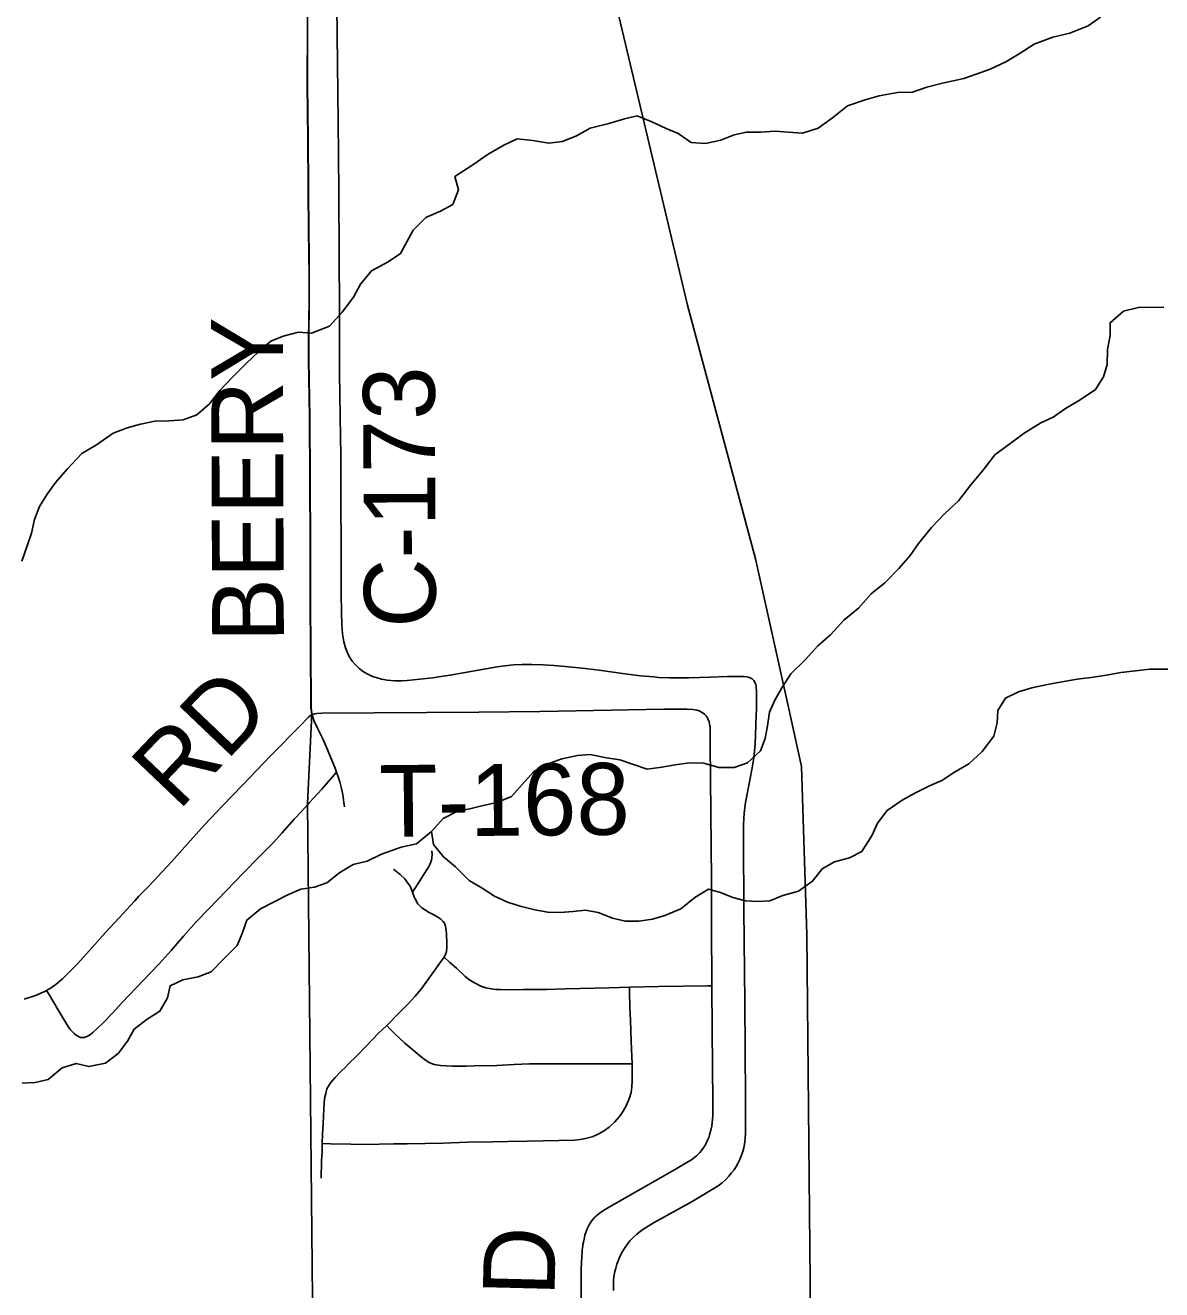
# Model space of a CAD drawing. Extents: x 0 to 34, y 0 to 22.
# Drawn here: x 27.697 to 28.598, y 10.604 to 11.606 of the extents above; entities that cross this region are included whole.
import ezdxf

# ---------------------------------------------------------------- set-up
doc = ezdxf.new("R2010")
doc.units = 0
for name, color, linetype in [('GM_X_Corporation', 7, 'Continuous'), ('GM_X_County_Road', 7, 'Continuous'), ('GM_X_County_Road_Text', 7, 'Continuous'), ('GM_X_Minor_River', 7, 'Continuous'), ('GM_X_Rail_Line', 7, 'Continuous'), ('GM_X_Township_Road', 7, 'Continuous'), ('GM_X_Township_Road_Text', 7, 'Continuous')]:
    doc.layers.add(name, color=color, linetype=linetype)

msp = doc.modelspace()

# ---------------------------------------------------------------- linework, layer by layer
at = {"layer": 'GM_X_Corporation'}
for points in [[(27.921, 11.6881), (27.921, 11.605), (27.9209, 11.5591), (27.9213, 11.5157), (27.922, 11.4402), (27.9221, 11.428), (27.9223, 11.4042), (27.9223, 11.3879), (27.922, 11.3573), (27.922, 11.3409), (27.9227, 11.2961), (27.9232, 11.1955), (27.9232, 11.1514), (27.9237, 11.0691), (27.9238, 11.0659), (27.9241, 11.0633), (27.9246, 11.0606), (27.9211, 10.9894), (27.9256, 10.5454), (27.929, 10.0627), (27.93, 9.9067), (29.8715, 9.9067), (29.8715, 12.7899)], [(23.0715, 9.9067), (27.93, 9.9067), (27.929, 10.0627), (27.9256, 10.5454), (27.9211, 10.9894), (27.9246, 11.0606), (27.9241, 11.0633), (27.9238, 11.0659), (27.9237, 11.0691), (27.9232, 11.1514), (27.9232, 11.1955), (27.9227, 11.2961), (27.922, 11.3409), (27.922, 11.3573), (27.9223, 11.3879), (27.9223, 11.4042), (27.9221, 11.428), (27.922, 11.4402), (27.9213, 11.5157), (27.9209, 11.5591), (27.921, 11.605), (27.921, 11.6881)]]:
    msp.add_lwpolyline(points, dxfattribs=at)
at = {"layer": 'GM_X_County_Road'}
for points in [[(27.9248, 11.06), (27.9243, 11.0628), (27.924, 11.0654), (27.9239, 11.0685), (27.9234, 11.1508), (27.9234, 11.1949), (27.9229, 11.2955), (27.9222, 11.3403), (27.9222, 11.3568), (27.9225, 11.3874), (27.9225, 11.4036), (27.9223, 11.4275), (27.9222, 11.4396), (27.9215, 11.5151), (27.9211, 11.5586), (27.9212, 11.6045), (27.9212, 11.6876)], [(27.7142, 10.8413), (27.7179, 10.8436), (27.7219, 10.8464), (27.727, 10.8507), (27.7388, 10.8625), (27.7505, 10.8754), (27.7608, 10.887), (27.7718, 10.8989), (27.7805, 10.9084), (27.7842, 10.9125), (27.7875, 10.9161), (27.7886, 10.9171), (27.7944, 10.9229), (27.7996, 10.9284), (27.8057, 10.9351), (27.8136, 10.9435), (27.8219, 10.9527), (27.8396, 10.9726), (27.8541, 10.9879), (27.8696, 11.0039), (27.892, 11.0276), (27.9161, 11.0518), (27.9205, 11.0566), (27.9219, 11.058), (27.9234, 11.0593), (27.9248, 11.06)], [(27.9441, 11.0143), (27.9429, 11.0175), (27.9396, 11.0257), (27.9371, 11.0316), (27.9332, 11.0406), (27.9289, 11.0492), (27.9264, 11.0547), (27.9255, 11.0572), (27.9248, 11.06)], [(27.9207, 10.9881), (27.9213, 10.9888), (27.9226, 10.9902), (27.9261, 10.9941), (27.9325, 11.0008), (27.941, 11.0107), (27.9441, 11.0143)], [(27.9505, 10.9869), (27.95, 10.9903), (27.949, 10.9966), (27.948, 11.0013), (27.9466, 11.0066), (27.9454, 11.0105), (27.9441, 11.0143)], [(27.7396, 10.8049), (27.7413, 10.8043), (27.7429, 10.8042), (27.7445, 10.8043), (27.7455, 10.8046), (27.7477, 10.8056), (27.7507, 10.8078), (27.7543, 10.8111), (27.7592, 10.8159), (27.7665, 10.8235), (27.7741, 10.8315), (27.7912, 10.8495), (27.8036, 10.8624), (27.8131, 10.873), (27.8229, 10.8844), (27.833, 10.8957), (27.8429, 10.906), (27.8567, 10.9203), (27.8704, 10.9346), (27.8828, 10.9472), (27.8941, 10.9585), (27.9007, 10.9659), (27.9105, 10.977), (27.9162, 10.9832), (27.9186, 10.9858), (27.9207, 10.9881)], [(28.0042, 10.9192), (28.0057, 10.9214), (28.0101, 10.9283), (28.013, 10.9329), (28.0165, 10.9384), (28.017, 10.9391), (28.0179, 10.9411), (28.0193, 10.9445), (28.0196, 10.9465), (28.0199, 10.9491), (28.0196, 10.952)], [(28.0042, 10.9192), (28.004, 10.92), (28.0036, 10.9213), (28.0024, 10.9239), (28.0007, 10.9265), (27.9981, 10.9299), (27.9944, 10.9332), (27.9892, 10.9376)], [(28.0293, 10.8678), (28.0308, 10.8707), (28.0313, 10.8724), (28.0315, 10.8754), (28.0314, 10.8807), (28.0313, 10.884), (28.0312, 10.8864), (28.031, 10.8888), (28.0304, 10.8924), (28.0297, 10.8946), (28.0286, 10.896), (28.0268, 10.8978), (28.0243, 10.8996), (28.0217, 10.9011), (28.0176, 10.9032), (28.0137, 10.9055), (28.0118, 10.9068), (28.01, 10.9085), (28.0086, 10.9101), (28.0063, 10.9139), (28.0056, 10.9156), (28.0045, 10.9184), (28.0042, 10.9192)], [(27.9839, 10.8137), (27.9861, 10.8158), (27.9918, 10.8218), (28.0014, 10.8314), (28.0062, 10.8366), (28.0111, 10.8425), (28.0165, 10.8499), (28.0226, 10.8584), (28.0261, 10.8635), (28.0293, 10.8678)], [(28.0293, 10.8678), (28.0339, 10.8637), (28.0391, 10.859), (28.0461, 10.8524), (28.0497, 10.8497), (28.054, 10.8472), (28.0585, 10.8449), (28.0623, 10.8435), (28.0665, 10.8428), (28.0702, 10.8423), (28.074, 10.8421), (28.0833, 10.8419), (28.092, 10.8421), (28.1105, 10.8422), (28.1254, 10.8426), (28.1602, 10.8435), (28.1762, 10.844)], [(27.6965, 10.8346), (27.7064, 10.8378), (27.7098, 10.8392), (27.7134, 10.8408), (27.7142, 10.8413)], [(27.7396, 10.8049), (27.7377, 10.806), (27.7361, 10.8074), (27.7345, 10.8089), (27.733, 10.8106), (27.7315, 10.8129), (27.7293, 10.8164), (27.7231, 10.8268), (27.7178, 10.8358), (27.7171, 10.8368), (27.7142, 10.8413)], [(28.1762, 10.844), (28.1993, 10.8446), (28.2379, 10.8451), (28.2415, 10.8452)], [(28.1782, 10.7834), (28.1781, 10.7891), (28.1779, 10.7952), (28.1776, 10.8013), (28.177, 10.818), (28.1766, 10.8278), (28.1763, 10.8407), (28.1762, 10.844)], [(27.9326, 10.7201), (27.9331, 10.728), (27.9335, 10.7357), (27.9338, 10.7421), (27.9339, 10.7475), (27.9344, 10.7525), (27.9346, 10.7559), (27.9355, 10.7599), (27.9364, 10.7636), (27.9392, 10.7682), (27.9429, 10.7724), (27.9478, 10.7775), (27.9511, 10.7808), (27.9536, 10.7832), (27.96, 10.7895), (27.9676, 10.7972), (27.9773, 10.8075), (27.9808, 10.8109), (27.9839, 10.8137)], [(27.9839, 10.8137), (27.9864, 10.8111), (27.9905, 10.8068), (27.994, 10.8036), (27.9982, 10.7998), (28.0015, 10.797), (28.0046, 10.7943), (28.0097, 10.79), (28.0135, 10.7869), (28.0154, 10.7857), (28.018, 10.7842), (28.0215, 10.7828), (28.0265, 10.782), (28.036, 10.7814), (28.0467, 10.7814), (28.0534, 10.7816), (28.0711, 10.7821), (28.0847, 10.7829), (28.097, 10.7832), (28.1106, 10.7834), (28.1174, 10.7834), (28.1254, 10.7834), (28.1515, 10.7834), (28.1638, 10.7834), (28.1699, 10.7834), (28.1782, 10.7834)], [(27.9326, 10.7201), (27.9392, 10.72), (27.9555, 10.7196), (27.9665, 10.7195), (27.9895, 10.7199), (28.0001, 10.72), (28.0285, 10.7205), (28.0479, 10.7213), (28.068, 10.7216), (28.0799, 10.7217), (28.095, 10.722), (28.1327, 10.7229), (28.137, 10.7234), (28.1413, 10.7242), (28.1467, 10.7256), (28.1513, 10.7275), (28.1556, 10.7299), (28.1602, 10.7332), (28.1647, 10.7374), (28.1684, 10.7416), (28.1712, 10.7458), (28.1737, 10.7507), (28.1762, 10.7564), (28.1774, 10.7606), (28.178, 10.7649), (28.1783, 10.7705), (28.1782, 10.7834)], [(27.9319, 10.6927), (27.9323, 10.7064), (27.9327, 10.7138), (27.9326, 10.7187), (27.9326, 10.7201)]]:
    msp.add_lwpolyline(points, dxfattribs=at)
at = {"layer": 'GM_X_Minor_River'}
for points in [[(28.5116, 11.5964), (28.5252, 11.5996), (28.5395, 11.6055), (28.5493, 11.6124)], [(27.6948, 11.1814), (27.6989, 11.1936), (27.7025, 11.2035), (27.7047, 11.2145), (27.7087, 11.2248), (27.7147, 11.2344), (27.7218, 11.244), (27.7307, 11.2543), (27.7423, 11.2666), (27.754, 11.2736), (27.7672, 11.2828), (27.7781, 11.2871), (27.7887, 11.2899), (27.8, 11.2923), (27.8114, 11.2925), (27.8227, 11.2934), (27.8333, 11.2973), (27.8434, 11.3061), (27.8516, 11.3165), (27.8621, 11.3276), (27.8726, 11.338), (27.8823, 11.3472), (27.8921, 11.3557), (27.9019, 11.3596), (27.914, 11.3628), (27.9242, 11.3621), (27.9385, 11.3676), (27.9486, 11.3787), (27.9576, 11.3906), (27.9631, 11.4009), (27.9717, 11.4113), (27.9849, 11.4186), (27.9947, 11.4252), (28.0047, 11.4436), (28.0148, 11.4535), (28.0265, 11.4586), (28.0363, 11.464), (28.0407, 11.4755), (28.0379, 11.4861), (28.0522, 11.4954), (28.0642, 11.5039), (28.0767, 11.5108), (28.0872, 11.5159), (28.0997, 11.5145), (28.1122, 11.5124), (28.1232, 11.5137), (28.1341, 11.5183), (28.1451, 11.5245), (28.1598, 11.5281), (28.1722, 11.5317), (28.1824, 11.5341), (28.1939, 11.5293), (28.2053, 11.5241), (28.2148, 11.5201), (28.2251, 11.513), (28.2365, 11.5123), (28.2486, 11.5148), (28.2591, 11.5191), (28.2689, 11.5211), (28.2799, 11.5212), (28.2917, 11.5221), (28.3019, 11.5211), (28.3133, 11.5204), (28.3257, 11.5244), (28.337, 11.5325), (28.349, 11.5421), (28.363, 11.5468), (28.3739, 11.55), (28.3886, 11.5525), (28.4004, 11.553), (28.4117, 11.5569), (28.4242, 11.5601), (28.4412, 11.5637), (28.451, 11.5672), (28.4619, 11.5712), (28.4743, 11.577), (28.4849, 11.5832), (28.4969, 11.5909), (28.5116, 11.5964)], [(28.4571, 11.2545), (28.4657, 11.2656), (28.4785, 11.2752), (28.489, 11.2829), (28.5022, 11.2911), (28.512, 11.2954), (28.5217, 11.3023), (28.5334, 11.3093), (28.5454, 11.3174), (28.5518, 11.3273), (28.5547, 11.3372), (28.5549, 11.349), (28.5571, 11.3601), (28.557, 11.3703), (28.5675, 11.3795), (28.5796, 11.3823), (28.5996, 11.3826)], [(27.6949, 10.7679), (27.7052, 10.7684), (27.7157, 10.7708), (27.7266, 10.7801), (27.7379, 10.7836), (27.7478, 10.7811), (27.761, 10.7839), (27.7712, 10.7916), (27.7786, 10.8012), (27.7838, 10.8107), (27.794, 10.8188), (27.8041, 10.825), (27.8101, 10.8357), (27.8122, 10.8452), (27.8224, 10.8499), (27.8345, 10.8523), (27.8447, 10.8562), (27.8548, 10.8666), (27.8653, 10.877), (27.8693, 10.8865), (27.873, 10.8972), (27.8839, 10.9061), (27.8937, 10.9111), (27.9061, 10.9173), (27.9159, 10.9216), (27.9265, 10.9233), (27.9363, 10.9268), (27.9468, 10.9349), (27.9573, 10.9411), (27.9683, 10.9439), (27.9796, 10.9493), (27.9954, 10.9548), (28.0075, 10.9576), (28.0192, 10.9672), (28.0285, 10.9776), (28.0398, 10.9834), (28.0496, 10.9854), (28.0602, 10.9879), (28.0712, 10.9903), (28.0828, 10.995), (28.0911, 11.0045), (28.1004, 11.0149), (28.111, 11.0207), (28.1227, 11.025), (28.1351, 11.0275), (28.145, 11.0283), (28.1579, 11.0258), (28.1685, 11.024), (28.1795, 11.0204), (28.1902, 11.0167), (28.2019, 11.0184), (28.2125, 11.02), (28.2238, 11.0217), (28.2352, 11.0214), (28.247, 11.0181), (28.2591, 11.0179), (28.2696, 11.0218), (28.2801, 11.0311), (28.2838, 11.041), (28.2856, 11.0509), (28.287, 11.0619), (28.2914, 11.0714), (28.297, 11.081), (28.3041, 11.0921), (28.3153, 11.1032), (28.3254, 11.1144), (28.3355, 11.1232), (28.346, 11.1347), (28.3576, 11.1443), (28.3677, 11.1555), (28.3786, 11.1643), (28.3895, 11.1755), (28.3985, 11.1858), (28.4052, 11.1954), (28.4156, 11.208), (28.4261, 11.2192), (28.437, 11.2292), (28.4467, 11.2418), (28.4571, 11.2545)], [(28.0192, 10.9672), (28.0208, 10.957), (28.0288, 10.9472), (28.0384, 10.9394), (28.0491, 10.9285), (28.0594, 10.9225), (28.0693, 10.9162), (28.0796, 10.9114), (28.0895, 10.9081), (28.1013, 10.9052), (28.1115, 10.9034), (28.1214, 10.9031), (28.1316, 10.904), (28.1414, 10.9049), (28.1513, 10.9031), (28.1627, 10.8987), (28.173, 10.8962), (28.1836, 10.8963), (28.1945, 10.8979), (28.2043, 10.9007), (28.2168, 10.9062), (28.228, 10.915), (28.2389, 10.9216), (28.2484, 10.9191), (28.258, 10.915), (28.2682, 10.9125), (28.2777, 10.9118), (28.2875, 10.9123), (28.2977, 10.9166), (28.3102, 10.9202), (28.3211, 10.9279), (28.3289, 10.9378), (28.3387, 10.9433), (28.3504, 10.9465), (28.3602, 10.9515), (28.3684, 10.9645), (28.3728, 10.974), (28.3803, 10.984), (28.3923, 10.9921), (28.4028, 10.9979), (28.4138, 11.0034), (28.4236, 11.0077), (28.4337, 11.0142), (28.445, 11.0208), (28.4555, 11.0308), (28.4648, 11.0427), (28.4674, 11.0534), (28.468, 11.0632), (28.474, 11.0728), (28.4845, 11.0779), (28.4951, 11.081), (28.5075, 11.0838), (28.5174, 11.0855), (28.531, 11.0879), (28.5419, 11.0892), (28.5525, 11.0908), (28.5654, 11.0932), (28.5771, 11.0945), (28.5885, 11.0958), (28.6028, 11.096)]]:
    msp.add_lwpolyline(points, dxfattribs=at)
at = {"layer": 'GM_X_Rail_Line'}
msp.add_lwpolyline([(28.1314, 11.7668), (28.2222, 11.3843), (28.276, 11.1832), (28.302, 11.0668), (28.3126, 11.0187), (28.3168, 10.8858), (28.3206, 10.4739), (28.3218, 10.0678), (28.3164, 10.0296), (28.3055, 9.997), (28.289, 9.9687), (28.2676, 9.9404), (28.2321, 9.9067)], dxfattribs=at)
at = {"layer": 'GM_X_Township_Road'}
for points in [[(28.2767, 11.0636), (28.2767, 11.0696), (28.2767, 11.0782), (28.2766, 11.0813), (28.2765, 11.0827), (28.2762, 11.0838), (28.2758, 11.0849), (28.2753, 11.086), (28.2746, 11.087), (28.2737, 11.0879), (28.2728, 11.0885), (28.2719, 11.089), (28.271, 11.0894), (28.2702, 11.0896), (28.2692, 11.0898), (28.2667, 11.0901), (28.2618, 11.0902), (28.2537, 11.09), (28.2401, 11.0895), (28.2233, 11.089), (28.2152, 11.089), (28.2115, 11.089), (28.2078, 11.0891), (28.1991, 11.0894), (28.1954, 11.0897), (28.1849, 11.0906), (28.1707, 11.0925), (28.1523, 11.0952), (28.1387, 11.0967), (28.1252, 11.098), (28.1166, 11.0987), (28.1077, 11.0993), (28.099, 11.0996), (28.0911, 11.0995), (28.0842, 11.0992), (28.0773, 11.0985), (28.0713, 11.0977), (28.0578, 11.0954), (28.034, 11.0912), (28.0285, 11.0903), (28.0236, 11.0896), (28.0205, 11.0891), (28.01, 11.0879), (28.0001, 11.087), (27.9958, 11.0867), (27.9902, 11.0866), (27.9841, 11.0872), (27.9798, 11.088), (27.9762, 11.089), (27.9727, 11.0902), (27.9693, 11.0917), (27.9655, 11.0939), (27.962, 11.0965), (27.9589, 11.0995), (27.9565, 11.1023), (27.9541, 11.106), (27.9527, 11.1088), (27.9512, 11.1128), (27.9499, 11.1176), (27.9489, 11.1238), (27.9483, 11.1312), (27.9479, 11.1411), (27.9478, 11.1554), (27.9478, 11.1685), (27.9478, 11.1803), (27.9477, 11.1883), (27.9474, 11.2329), (27.9476, 11.2509), (27.9476, 11.2657), (27.9473, 11.28), (27.9469, 11.2962), (27.9464, 11.3303), (27.9464, 11.3787), (27.946, 11.473), (27.9457, 11.5034), (27.9453, 11.5295), (27.9438, 11.6675)], [(27.9248, 11.06), (27.9266, 11.0605), (27.9285, 11.0609), (27.9325, 11.0611), (28.0568, 11.0619), (28.1051, 11.0624), (28.1197, 11.0627), (28.2035, 11.0642), (28.2161, 11.0643), (28.2217, 11.0642), (28.2263, 11.0639), (28.2295, 11.0634), (28.2313, 11.0628), (28.2325, 11.0623), (28.2336, 11.0617), (28.2347, 11.061), (28.2355, 11.0603), (28.2361, 11.0598), (28.2369, 11.0589), (28.2373, 11.0583)], [(28.1635, 10.6037), (28.1635, 10.6086), (28.1636, 10.6122), (28.1641, 10.6161), (28.1646, 10.6189), (28.1653, 10.6216), (28.1662, 10.6246), (28.1684, 10.63), (28.1699, 10.6333), (28.172, 10.6368), (28.1743, 10.6403), (28.1765, 10.6431), (28.1795, 10.646), (28.1817, 10.6481), (28.1837, 10.6497), (28.1869, 10.6522), (28.191, 10.6548), (28.1957, 10.6577), (28.2258, 10.6744), (28.2464, 10.6868), (28.2495, 10.6891), (28.2523, 10.6914), (28.255, 10.6944), (28.2571, 10.6969), (28.2591, 10.6993), (28.2607, 10.7019), (28.2621, 10.7043), (28.2636, 10.7075), (28.2648, 10.7104), (28.2659, 10.714), (28.2669, 10.7168), (28.2674, 10.7196), (28.2679, 10.7239), (28.2682, 10.729), (28.268, 10.756), (28.2676, 10.8322), (28.2668, 10.9056), (28.2666, 10.9604), (28.2666, 10.9671), (28.2666, 10.9725), (28.2668, 10.9773), (28.2671, 10.9822), (28.2682, 10.9902), (28.2701, 11.0012), (28.2725, 11.0134), (28.2733, 11.0177), (28.2747, 11.0256), (28.2753, 11.0312), (28.2757, 11.0367), (28.276, 11.0438), (28.2766, 11.0597), (28.2767, 11.0636)], [(28.2415, 10.8452), (28.2413, 10.8935), (28.2411, 10.9291), (28.2402, 11.036), (28.2402, 11.0475), (28.24, 11.0496), (28.24, 11.0503), (28.2399, 11.051), (28.2397, 11.0524), (28.2392, 11.0545), (28.2389, 11.0552), (28.2383, 11.0565), (28.2377, 11.0578), (28.2373, 11.0583)], [(28.1379, 10.5885), (28.138, 10.6206), (28.1382, 10.6262), (28.1384, 10.6307), (28.1386, 10.6339), (28.1388, 10.6363), (28.139, 10.6373), (28.1392, 10.6391), (28.1393, 10.6401), (28.1397, 10.6421), (28.1402, 10.6444), (28.1409, 10.6475), (28.1418, 10.6504), (28.1427, 10.6527), (28.1434, 10.6543), (28.1442, 10.6558), (28.1455, 10.6579), (28.1469, 10.6598), (28.1482, 10.6613), (28.1491, 10.6622), (28.1503, 10.6633), (28.1523, 10.6649), (28.1548, 10.6667), (28.1591, 10.6693), (28.1855, 10.6843), (28.2132, 10.7001), (28.2229, 10.7059), (28.2253, 10.7074), (28.2267, 10.7084), (28.2281, 10.7095), (28.2294, 10.7105), (28.2304, 10.7115), (28.2319, 10.7131), (28.2332, 10.7146), (28.2345, 10.7165), (28.2363, 10.7191), (28.237, 10.7206), (28.2378, 10.722), (28.2384, 10.7235), (28.2392, 10.7254), (28.2397, 10.727), (28.2407, 10.7308), (28.2414, 10.7343), (28.2417, 10.7366), (28.242, 10.7396), (28.2422, 10.7419), (28.2423, 10.7454), (28.2423, 10.7529), (28.2417, 10.8105), (28.2415, 10.8452)]]:
    msp.add_lwpolyline(points, dxfattribs=at)

# ---------------------------------------------------------------- texts
at = {"layer": 'GM_X_County_Road_Text'}
for s, rotation, p in [('BEERY', 90.2088, (27.9024, 11.1174)), ('C-173', 90.2733, (28.0228, 11.1288)), ('RD', 46.3805, (27.8187, 10.9829))]:
    msp.add_text(s, height=0.05682, rotation=rotation, dxfattribs=at).set_placement(p)
at = {"layer": 'GM_X_Township_Road_Text'}
for s, height, rotation, p in [('T-168', 0.05682, 0.5631, (27.9781, 10.963)), ('D', 0.0568, 88.5792, (28.1167, 10.5988))]:
    msp.add_text(s, height=height, rotation=rotation, dxfattribs=at).set_placement(p)

doc.saveas('drawing.dxf')
